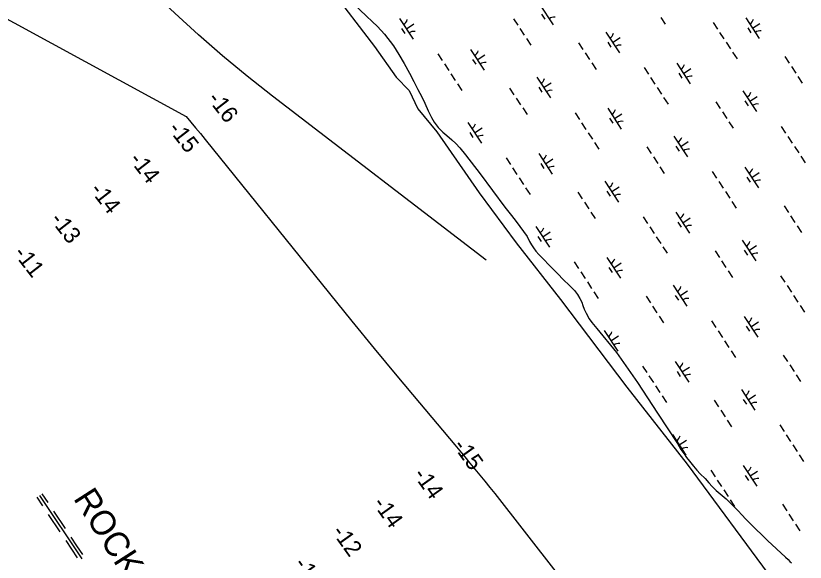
# Model space of a CAD drawing. Extents: x 3945642 to 3966284, y 206476 to 228921.
# Drawn here: x 3953528 to 3955120, y 220127 to 221229 of the extents above; entities that cross this region are included whole.
import ezdxf

# ---------------------------------------------------------------- set-up
doc = ezdxf.new("R2010")
doc.units = 0
for name, color, linetype in [('V-RIVR-EDGE', 7, 'Continuous'), ('V-RIVR-RANG', 7, 'Continuous'), ('V-RRAP-DIKE', 7, 'Continuous'), ('V-RRAP-SILL-IDEN', 7, 'Continuous'), ('V-TOPO-MINR', 7, 'Continuous'), ('V-WETL-SWMP', 7, 'Continuous')]:
    doc.layers.add(name, color=color, linetype=linetype)

msp = doc.modelspace()

# ---------------------------------------------------------------- linework, layer by layer
at = {"layer": 'V-RIVR-EDGE'}
msp.add_lwpolyline([(3954160.7, 221285.9), (3954250.9, 221167.2), (3954294.8, 221105.5), (3954320.9, 221078.2), (3954338.7, 221041.4), (3954376.7, 220995.1), (3954462.2, 220871.6), (3954537, 220770.7), (3954626, 220656.7), (3954760.2, 220479.8), (3954881.3, 220324.3), (3955054.6, 220090.4)], dxfattribs=at)
at = {"layer": 'V-RRAP-DIKE'}
for points in [[(3953570.1, 220257.7), (3953581.8, 220240.2)], [(3953575.3, 220261.2), (3953660.7, 220133.1)], [(3953580.5, 220264.6), (3953592.2, 220247.2)], [(3953603.8, 220229.7), (3953627.1, 220194.7)], [(3953593.4, 220222.7), (3953616.7, 220187.8)], [(3953638.8, 220177.3), (3953650.4, 220159.8)], [(3953628.4, 220170.3), (3953640, 220152.9)], [(3953640, 220152.9), (3953651.7, 220135.4)], [(3953650.4, 220159.8), (3953662.1, 220142.3)]]:
    msp.add_lwpolyline(points, dxfattribs=at)
at = {"layer": 'V-TOPO-MINR'}
for points in [[(3954476.2, 220735.7), (3954045.2, 221066.7), (3953994.5, 221106.9), (3953944.6, 221148), (3953896, 221190.6), (3953848.3, 221234.2), (3953801.3, 221278.7), (3953754.6, 221323.6), (3953708.3, 221368.8), (3953662.3, 221414.3), (3953443.5, 221632.4)], [(3953252.6, 221363.5), (3953871.3, 221025.9), (3953881, 221014.4), (3953890.5, 221002.9), (3953900, 220991.3), (3953909.4, 220979.7), (3954160.6, 220668.4), (3954205.5, 220613), (3954250.6, 220557.8), (3954296.1, 220502.9), (3954341.8, 220448.2), (3954413, 220363.2), (3954423.2, 220351.1), (3954433.4, 220338.9), (3954443.5, 220326.7), (3954453.7, 220314.4), (3954463.8, 220302.2), (3954473.8, 220289.8), (3954483.7, 220277.4), (3954493.5, 220264.9), (3955049.9, 219551)]]:
    msp.add_lwpolyline(points, dxfattribs=at)
at = {"layer": 'V-WETL-SWMP'}
for p, q in [((3954208.2, 221254), (3954234.7, 221228.2)), ((3954583.9, 221252.4), (3954611.3, 221210.5)), ((3954234.7, 221228.2), (3954246.5, 221217.4)), ((3954587.8, 221232.3), (3954594.4, 221222.2)), ((3954246.5, 221217.4), (3954257, 221207.2)), ((3954301.7, 221223.8), (3954329.1, 221181.9)), ((3954315.4, 221202.9), (3954330.4, 221212.7)), ((3954531.2, 221223.2), (3954540, 221209.8)), ((3954828.2, 221225.3), (3954837, 221211.9)), ((3954933.9, 221215.6), (3954942.6, 221202.2)), ((3954999.7, 221224.8), (3955027.1, 221182.9)), ((3955013.4, 221203.8), (3955028.4, 221213.7)), ((3954257, 221207.2), (3954271, 221191.9)), ((3954305.6, 221203.6), (3954312.2, 221193.6)), ((3954544.4, 221203.1), (3954553.1, 221189.7)), ((3954717.5, 221196.1), (3954744.9, 221154.3)), ((3954947, 221195.6), (3954955.8, 221182.2)), ((3955003.6, 221204.6), (3955010.2, 221194.6)), ((3954271, 221191.9), (3954289.7, 221168.6)), ((3954557.5, 221183), (3954566.3, 221169.6)), ((3954731.2, 221175.2), (3954746.2, 221185.1)), ((3954289.7, 221168.6), (3954300.2, 221150.9)), ((3954662.8, 221174.3), (3954671.5, 221160.9)), ((3954721.4, 221176), (3954728, 221166)), ((3954960.2, 221175.5), (3954968.9, 221162.1)), ((3954300.2, 221150.9), (3954311.1, 221132.5)), ((3954378.9, 221152.1), (3954387.7, 221138.7)), ((3954444.7, 221161.2), (3954472.1, 221119.4)), ((3954458.4, 221140.3), (3954473.5, 221150.2)), ((3954675.9, 221154.2), (3954684.7, 221140.9)), ((3954973.3, 221155.4), (3954982.1, 221142)), ((3954311.1, 221132.5), (3954321.8, 221113.4)), ((3954392.1, 221132), (3954400.9, 221118.6)), ((3954448.7, 221141.1), (3954455.3, 221131.1)), ((3954689.1, 221134.2), (3954697.8, 221120.8)), ((3954860.5, 221133.6), (3954887.9, 221091.8)), ((3955078.6, 221146.7), (3955087.3, 221133.3)), ((3954794.7, 221124.5), (3954803.5, 221111.1)), ((3954874.2, 221112.7), (3954889.3, 221122.6)), ((3955091.7, 221126.6), (3955100.5, 221113.2)), ((3954321.8, 221113.4), (3954330.6, 221096.6)), ((3954405.2, 221111.9), (3954414, 221098.6)), ((3954578.3, 221105), (3954605.7, 221063.2)), ((3954807.9, 221104.4), (3954816.7, 221091)), ((3954864.5, 221113.5), (3954871.1, 221103.4)), ((3955104.9, 221106.5), (3955113.6, 221093.2)), ((3954330.6, 221096.6), (3954338.6, 221080.6)), ((3954418.4, 221091.9), (3954427.2, 221078.5)), ((3954582.3, 221084.9), (3954588.8, 221074.8)), ((3954592, 221084.1), (3954607.1, 221093.9)), ((3954821, 221084.3), (3954829.8, 221070.9)), ((3954338.6, 221080.6), (3954346.5, 221065.8)), ((3954523.6, 221083.2), (3954532.4, 221069.8)), ((3954994.1, 221077.4), (3955021.5, 221035.6)), ((3954346.5, 221065.8), (3954352.8, 221052.9)), ((3954352.8, 221052.9), (3954359.4, 221037.4)), ((3954536.8, 221063.1), (3954545.5, 221049.7)), ((3954834.2, 221064.3), (3954843, 221050.9)), ((3954939.4, 221055.5), (3954948.2, 221042.2)), ((3954998.1, 221057.3), (3955004.6, 221047.2)), ((3955007.8, 221056.5), (3955022.9, 221066.3)), ((3954359.4, 221037.4), (3954365.8, 221023.7)), ((3954549.9, 221043), (3954558.7, 221029.6)), ((3954721.4, 221042.5), (3954748.8, 221000.6)), ((3954365.8, 221023.7), (3954371.3, 221014.2)), ((3954655.6, 221033.3), (3954664.4, 221019.9)), ((3954725.3, 221022.3), (3954731.9, 221012.3)), ((3954735.1, 221021.5), (3954750.1, 221031.4)), ((3954952.6, 221035.5), (3954961.3, 221022.1)), ((3954371.3, 221014.2), (3954379.5, 221003.7)), ((3954439.2, 221013.8), (3954466.6, 220972)), ((3954668.7, 221013.3), (3954677.5, 220999.9)), ((3954965.7, 221015.4), (3954974.5, 221002)), ((3955071.4, 221005.7), (3955080.2, 220992.3)), ((3954379.5, 221003.7), (3954388.9, 220994.1)), ((3954388.9, 220994.1), (3954396.7, 220987.2)), ((3954443.1, 220993.7), (3954449.7, 220983.7)), ((3954452.9, 220992.9), (3954467.9, 221002.8)), ((3954681.9, 220993.2), (3954690.7, 220979.8)), ((3954396.7, 220987.2), (3954407.2, 220978.5)), ((3954407.2, 220978.5), (3954415.2, 220971.1)), ((3954695, 220973.1), (3954703.8, 220959.7)), ((3954855, 220986.2), (3954882.4, 220944.4)), ((3954868.7, 220965.3), (3954883.7, 220975.2)), ((3955084.5, 220985.6), (3955093.3, 220972.3)), ((3954415.2, 220971.1), (3954422.9, 220962.6)), ((3954422.9, 220962.6), (3954434.7, 220948.3)), ((3954800.3, 220964.4), (3954809, 220951)), ((3954858.9, 220966.1), (3954865.5, 220956.1)), ((3955097.7, 220965.6), (3955106.5, 220952.2)), ((3954434.7, 220948.3), (3954464, 220910.1)), ((3954516.5, 220942.2), (3954525.2, 220928.8)), ((3954582.2, 220951.3), (3954609.6, 220909.5)), ((3954813.4, 220944.3), (3954822.2, 220930.9)), ((3955110.8, 220945.5), (3955119.6, 220932.1)), ((3954586.2, 220931.2), (3954592.8, 220921.1)), ((3954595.9, 220930.4), (3954611, 220940.3)), ((3954464, 220910.1), (3954514, 220842.7)), ((3954529.6, 220922.1), (3954538.4, 220908.7)), ((3954826.6, 220924.2), (3954835.4, 220910.9)), ((3954932.3, 220914.6), (3954941, 220901.2)), ((3954998, 220923.7), (3955025.4, 220881.9)), ((3955011.7, 220902.8), (3955026.8, 220912.6)), ((3954542.8, 220902), (3954551.5, 220888.6)), ((3954715.8, 220895.1), (3954743.2, 220853.3)), ((3954945.4, 220894.5), (3954954.2, 220881.1)), ((3955002, 220903.6), (3955008.6, 220893.5)), ((3954555.9, 220882), (3954564.7, 220868.6)), ((3954729.5, 220874.2), (3954744.6, 220884)), ((3954661.1, 220873.2), (3954669.9, 220859.9)), ((3954719.8, 220875), (3954726.4, 220864.9)), ((3954958.6, 220874.4), (3954967.3, 220861)), ((3954674.3, 220853.2), (3954683.1, 220839.8)), ((3954971.7, 220854.3), (3954980.5, 220841)), ((3955076.9, 220845.6), (3955085.7, 220832.2)), ((3954514, 220842.7), (3954527.5, 220826.1)), ((3954687.4, 220833.1), (3954696.2, 220819.7)), ((3954858.9, 220832.5), (3954886.3, 220790.7)), ((3954527.5, 220826.1), (3954537.1, 220814.1)), ((3954537.1, 220814.1), (3954559.1, 220783.4)), ((3954793.1, 220823.4), (3954801.9, 220810)), ((3954872.6, 220811.6), (3954887.7, 220821.5)), ((3955090.1, 220825.5), (3955098.9, 220812.2)), ((3954576.7, 220803.9), (3954604.1, 220762.1)), ((3954806.3, 220803.3), (3954815, 220790)), ((3954862.9, 220812.4), (3954869.4, 220802.4)), ((3955103.2, 220805.5), (3955112, 220792.1)), ((3954559.1, 220783.4), (3954564, 220773.8)), ((3954580.7, 220783.8), (3954587.2, 220773.8)), ((3954590.4, 220783), (3954605.5, 220792.9)), ((3954819.4, 220783.3), (3954828.2, 220769.9)), ((3954564, 220773.8), (3954567.5, 220767.2)), ((3954567.5, 220767.2), (3954571.5, 220761)), ((3954992.5, 220776.3), (3955019.9, 220734.5)), ((3954571.5, 220761), (3954576.7, 220754.3)), ((3954576.7, 220754.3), (3954582.6, 220747.6)), ((3954832.6, 220763.2), (3954841.3, 220749.8)), ((3954937.8, 220754.5), (3954946.6, 220741.1)), ((3954996.5, 220756.2), (3955003, 220746.2)), ((3955006.2, 220755.4), (3955021.2, 220765.3)), ((3954582.6, 220747.6), (3954587.8, 220741.8)), ((3954587.8, 220741.8), (3954594.3, 220735.1)), ((3954594.3, 220735.1), (3954600.4, 220728.9)), ((3954719.8, 220741.4), (3954747.2, 220699.6)), ((3954951, 220734.4), (3954959.7, 220721)), ((3954600.4, 220728.9), (3954608.9, 220720.5)), ((3954608.9, 220720.5), (3954616.3, 220713.3)), ((3954654, 220732.3), (3954662.7, 220718.9)), ((3954723.7, 220721.3), (3954730.3, 220711.2)), ((3954733.5, 220720.5), (3954748.5, 220730.3)), ((3954616.3, 220713.3), (3954623.2, 220705.7)), ((3954623.2, 220705.7), (3954628.8, 220699.5)), ((3954667.1, 220712.2), (3954675.9, 220698.8)), ((3954964.1, 220714.3), (3954972.9, 220700.9)), ((3955069.8, 220704.6), (3955078.5, 220691.3)), ((3954628.8, 220699.5), (3954646.9, 220682.2)), ((3954680.3, 220692.1), (3954689, 220678.7)), ((3954646.9, 220682.2), (3954654.1, 220674.8)), ((3954654.1, 220674.8), (3954660.7, 220666.5)), ((3954693.4, 220672), (3954702.2, 220658.6)), ((3954853.4, 220685.2), (3954880.8, 220643.3)), ((3954867.1, 220664.2), (3954882.1, 220674.1)), ((3955082.9, 220684.6), (3955091.7, 220671.2)), ((3954660.7, 220666.5), (3954665.3, 220658.8)), ((3954665.3, 220658.8), (3954668.9, 220651.1)), ((3954798.7, 220663.3), (3954807.4, 220649.9)), ((3954857.3, 220665), (3954863.9, 220655)), ((3955096.1, 220664.5), (3955104.8, 220651.1)), ((3954668.9, 220651.1), (3954671.1, 220644.5)), ((3954671.1, 220644.5), (3954673.8, 220637.4)), ((3954811.8, 220643.2), (3954820.6, 220629.9)), ((3955109.2, 220644.4), (3955118, 220631)), ((3954673.8, 220637.4), (3954677.7, 220628.7)), ((3954677.7, 220628.7), (3954684.2, 220617.9)), ((3954825, 220623.2), (3954833.7, 220609.8)), ((3954996.4, 220622.6), (3955023.8, 220580.8)), ((3954684.2, 220617.9), (3954689.2, 220610.5)), ((3954689.2, 220610.5), (3954699.6, 220597.8)), ((3954930.6, 220613.5), (3954939.4, 220600.1)), ((3955010.1, 220601.7), (3955025.2, 220611.6)), ((3954699.6, 220597.8), (3954739.3, 220549.8)), ((3954714.2, 220594), (3954741.6, 220552.2)), ((3954943.8, 220593.4), (3954952.6, 220580)), ((3955000.4, 220602.5), (3955007, 220592.5)), ((3954727.9, 220573.1), (3954743, 220583)), ((3954956.9, 220573.3), (3954965.7, 220560)), ((3954739.3, 220549.8), (3954781.4, 220489)), ((3954970.1, 220553.3), (3954978.9, 220539.9)), ((3955075.3, 220544.6), (3955084.1, 220531.2)), ((3954857.3, 220531.5), (3954884.7, 220489.6)), ((3954791.5, 220522.3), (3954800.3, 220509)), ((3954861.2, 220511.3), (3954867.8, 220501.3)), ((3954871, 220510.6), (3954886, 220520.4)), ((3955088.5, 220524.5), (3955097.2, 220511.1)), ((3954804.6, 220502.3), (3954813.4, 220488.9)), ((3955101.6, 220504.4), (3955110.4, 220491)), ((3954781.4, 220489), (3954822, 220427.1)), ((3954817.8, 220482.2), (3954826.6, 220468.8)), ((3954990.9, 220475.2), (3955018.3, 220433.4)), ((3955004.6, 220454.3), (3955019.6, 220464.2)), ((3954831, 220462.1), (3954839.7, 220448.7)), ((3954936.2, 220453.4), (3954945, 220440)), ((3954994.8, 220455.1), (3955001.4, 220445.1)), ((3954949.3, 220433.3), (3954958.1, 220419.9)), ((3954822, 220427.1), (3954862.2, 220366.2)), ((3954962.5, 220413.3), (3954971.3, 220399.9)), ((3955068.2, 220403.6), (3955076.9, 220390.2)), ((3954851.7, 220384.1), (3954879.1, 220342.3)), ((3955081.3, 220383.5), (3955090.1, 220370.1)), ((3954865.4, 220363.2), (3954880.5, 220373)), ((3954862.2, 220366.2), (3954868.9, 220353.8)), ((3954868.9, 220353.8), (3954875.4, 220344.9)), ((3955094.5, 220363.4), (3955103.2, 220350)), ((3954875.4, 220344.9), (3954880.5, 220337.7)), ((3954880.5, 220337.7), (3954886.3, 220330.4)), ((3955107.6, 220343.3), (3955116.4, 220330)), ((3954886.3, 220330.4), (3954894.3, 220320.2)), ((3954894.3, 220320.2), (3954901.2, 220312.3)), ((3954994.8, 220321.5), (3955022.2, 220279.7)), ((3954901.2, 220312.3), (3954908.1, 220305.2)), ((3954908.1, 220305.2), (3954917.8, 220295.2)), ((3954929, 220312.4), (3954937.8, 220299)), ((3955008.5, 220300.6), (3955023.6, 220310.5)), ((3954917.8, 220295.2), (3954925.4, 220287)), ((3954942.2, 220292.3), (3954950.9, 220279)), ((3954998.8, 220301.4), (3955005.3, 220291.4)), ((3954925.4, 220287), (3954932.1, 220279.6)), ((3954932.1, 220279.6), (3954940.4, 220271.2)), ((3954955.3, 220272.3), (3954964.1, 220258.9)), ((3954940.4, 220271.2), (3954960, 220254.3)), ((3954960, 220254.3), (3954970.5, 220244.3)), ((3954968.5, 220252.2), (3954977.2, 220238.8)), ((3954970.5, 220244.3), (3954978.7, 220236.1)), ((3955073.7, 220243.5), (3955082.5, 220230.1)), ((3954978.7, 220236.1), (3954984.3, 220230)), ((3954984.3, 220230), (3954991.9, 220222)), ((3954991.9, 220222), (3954999.7, 220213.7)), ((3954999.7, 220213.7), (3955008.7, 220204.4)), ((3955086.9, 220223.4), (3955095.6, 220210)), ((3955008.7, 220204.4), (3955043.4, 220170.3)), ((3955100, 220203.3), (3955108.8, 220189.9)), ((3955043.4, 220170.3), (3955079.9, 220137)), ((3955079.9, 220137), (3955085.2, 220131.8)), ((3955085.2, 220131.8), (3955088.9, 220128.3)), ((3955088.9, 220128.3), (3955092, 220125.3))]:
    msp.add_line(p, q, dxfattribs=at)
for centre, start, end in [((3954300.4, 221226.1), 302.4575, 344.0011), ((3954612.9, 221208.5), 82.4574, 124.0011), ((3954998.4, 221227.1), 302.4575, 344.0011), ((3954330.7, 221179.9), 82.4574, 124.0011), ((3955028.7, 221180.9), 82.4574, 124.0011), ((3954716.2, 221198.5), 302.4575, 344.0011), ((3954746.5, 221152.3), 82.4574, 124.0011), ((3954443.5, 221163.5), 302.4575, 344.0011), ((3954473.8, 221117.3), 82.4574, 124.0011), ((3954859.3, 221135.9), 302.4575, 344.0011), ((3954577.1, 221107.3), 302.4575, 344.0011), ((3954889.6, 221089.7), 82.4574, 124.0011), ((3954607.3, 221061.1), 82.4574, 124.0011), ((3954992.9, 221079.7), 302.4575, 344.0011), ((3954720.1, 221044.8), 302.4575, 344.0011), ((3955023.1, 221033.5), 82.4574, 124.0011), ((3954437.9, 221016.2), 302.4575, 344.0011), ((3954750.4, 220998.6), 82.4574, 124.0011), ((3954468.2, 220970), 82.4574, 124.0011), ((3954853.7, 220988.6), 302.4575, 344.0011), ((3954884, 220942.3), 82.4574, 124.0011), ((3954581, 220953.6), 302.4575, 344.0011), ((3954611.3, 220907.4), 82.4574, 124.0011), ((3954996.8, 220926), 302.4575, 344.0011), ((3955027.1, 220879.8), 82.4574, 124.0011), ((3954714.6, 220897.4), 302.4575, 344.0011), ((3954744.9, 220851.2), 82.4574, 124.0011), ((3954857.7, 220834.9), 302.4575, 344.0011), ((3954575.5, 220806.2), 302.4575, 344.0011), ((3954887.9, 220788.6), 82.4574, 124.0011), ((3954605.7, 220760), 82.4574, 124.0011), ((3954991.3, 220778.6), 302.4575, 344.0011), ((3955021.5, 220732.4), 82.4574, 124.0011), ((3954718.5, 220743.7), 302.4575, 344.0011), ((3954748.8, 220697.5), 82.4574, 124.0011), ((3954852.1, 220687.5), 302.4575, 344.0011), ((3954882.4, 220641.3), 82.4574, 124.0011), ((3954995.2, 220624.9), 302.4575, 344.0011), ((3954713, 220596.3), 302.4575, 344.0011), ((3955025.5, 220578.7), 82.4574, 124.0011), ((3954743.3, 220550.1), 82.4574, 124.0011), ((3954856.1, 220533.8), 302.4575, 344.0011), ((3954886.3, 220487.6), 82.4574, 124.0011), ((3954989.6, 220477.6), 302.4575, 344.0011), ((3955019.9, 220431.4), 82.4574, 124.0011), ((3954850.5, 220386.4), 302.4575, 344.0011), ((3954880.8, 220340.2), 82.4574, 124.0011), ((3954993.6, 220323.9), 302.4575, 344.0011), ((3955023.8, 220277.7), 82.4574, 124.0011)]:
    msp.add_arc(centre, 17.6, start, end, dxfattribs=at)

# ---------------------------------------------------------------- texts
at = {"layer": 'V-RIVR-RANG'}
for s, rotation, p in [('-16', 307.7594, (3953912.9, 221061.2)), ('-15', 307.7594, (3953833.5, 221000.6)), ('-14', 307.7594, (3953755, 220938.6)), ('-14', 307.7594, (3953675.9, 220877.4)), ('-13', 307.7594, (3953595.8, 220817.5)), ('-11', 307.7594, (3953521.9, 220749.4)), ('-15', 305.5434, (3954408.2, 220361.6)), ('-14', 305.5434, (3954327.8, 220303)), ('-14', 305.5434, (3954246.3, 220244.8)), ('-12', 305.5434, (3954163.8, 220187.6)), ('-11', 305.5434, (3954087.3, 220122.7))]:
    msp.add_text(s, height=33.5, rotation=rotation, dxfattribs=at).set_placement(p)
at = {"layer": 'V-RRAP-SILL-IDEN'}
msp.add_text('ROCK SILL', height=50, rotation=302.6757, dxfattribs=at).set_placement((3953642.7, 220255.2))

doc.saveas('drawing.dxf')
